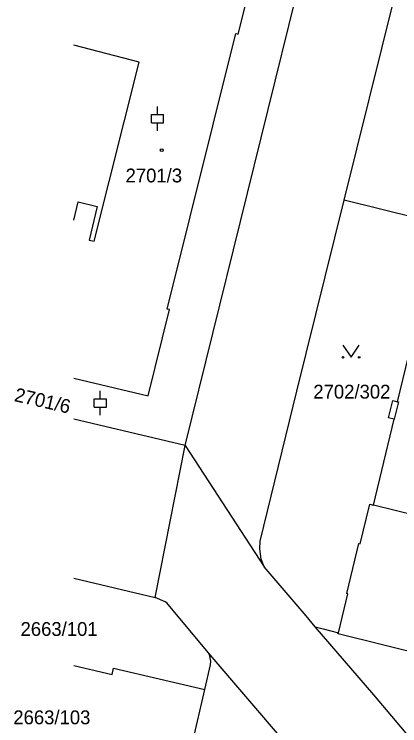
# Model space of a CAD drawing. Extents: x -496682 to -495907, y -1088575 to -1088018.
# Drawn here: x -496681.5 to -496634.1, y -1088524.5 to -1088436.9 of the extents above; entities that cross this region are included whole.
import ezdxf

# ---------------------------------------------------------------- set-up
doc = ezdxf.new("R2010")
doc.units = 0
for name, color, linetype in [('Hranice parcel', 7, 'Continuous'), ('Parcelní čísla', 7, 'Continuous'), ('Vnitřní kresba', 7, 'Continuous'), ('Značky budov', 7, 'Continuous'), ('Značky kultur', 7, 'Continuous')]:
    doc.layers.add(name, color=color, linetype=linetype)

msp = doc.modelspace()

# ---------------------------------------------------------------- linework, layer by layer
at = {"layer": 'Hranice parcel'}
for p, q in [((-496640.95, -1088459.81), (-496628.55, -1088409.94)), ((-496660.52, -1088489.98), (-496645.25, -1088428.29)), ((-496629.09, -1088462.74), (-496640.95, -1088459.81)), ((-496660.52, -1088489.98), (-496674.201, -1088486.739)), ((-496664.18, -1088508.68), (-496660.52, -1088489.98)), ((-496660.52, -1088489.98), (-496650.79, -1088504.94)), ((-496625.56, -1088500.2), (-496637.35, -1088497.34)), ((-496674.201, -1088506.316), (-496664.18, -1088508.68)), ((-496657.68, -1088515.47), (-496662.75, -1088509.37)), ((-496639.82, -1088536.3), (-496657.68, -1088515.47))]:
    msp.add_line(p, q, dxfattribs=at)
for points in [[(-496674.201, -1088481.706), (-496665.05, -1088483.89), (-496662.42, -1088473.27), (-496662.72, -1088473.21), (-496654.28, -1088439.31), (-496654, -1088439.38), (-496650.83, -1088426.78), (-496645.25, -1088428.29)], [(-496650.79, -1088504.94), (-496651.14, -1088503.97), (-496651.32, -1088502.72), (-496651.27, -1088501.75), (-496646.76, -1088483.31), (-496640.95, -1088459.81)], [(-496637.35, -1088497.34), (-496634.78, -1088486.77), (-496635.48, -1088486.6), (-496634.95, -1088484.46), (-496634.38, -1088484.6), (-496631.65, -1088473.31)], [(-496641.66, -1088513.05), (-496640.49, -1088508.23), (-496640.63, -1088508.19), (-496639.16, -1088502.05), (-496638.99, -1088502.09), (-496637.8, -1088497.21), (-496637.35, -1088497.34)], [(-496644.5, -1088512.3), (-496645.64, -1088510.97), (-496650.79, -1088504.94)], [(-496662.75, -1088509.37), (-496662.98, -1088509.24), (-496664.18, -1088508.68)], [(-496621.83, -1088538.93), (-496627.8, -1088531.94), (-496637.3, -1088520.68), (-496644.5, -1088512.3)], [(-496644.5, -1088512.3), (-496643.54, -1088512.55), (-496641.66, -1088513.05)], [(-496619.55, -1088518.48), (-496630.64, -1088516.04), (-496630.61, -1088515.92), (-496641.69, -1088513.15), (-496641.66, -1088513.05)], [(-496657.39, -1088516.99), (-496657.35, -1088516.539), (-496657.368, -1088516.313), (-496657.477, -1088515.874), (-496657.68, -1088515.47)], [(-496674.201, -1088517.051), (-496669.49, -1088518.17), (-496669.31, -1088517.4), (-496658.07, -1088520.03), (-496657.39, -1088516.99)]]:
    msp.add_lwpolyline(points, dxfattribs=at)
at = {"layer": 'Vnitřní kresba'}
for p, q in [((-496666.18, -1088442.82), (-496674.201, -1088440.723)), ((-496671.69, -1088464.87), (-496666.18, -1088442.82)), ((-496674.201, -1088462.263), (-496673.67, -1088460.03)), ((-496673.67, -1088460.03), (-496671.33, -1088460.58)), ((-496671.33, -1088460.58), (-496672.3, -1088464.73)), ((-496672.3, -1088464.73), (-496671.69, -1088464.87)), ((-496634.26, -1088484.62), (-496634.78, -1088486.77)), ((-496634.38, -1088484.6), (-496634.26, -1088484.62)), ((-496660.69, -1088531.17), (-496658.07, -1088520.03))]:
    msp.add_line(p, q, dxfattribs=at)
at = {"layer": 'Značky budov'}
msp.add_circle((-496663.387, -1088453.659), 0.175, dxfattribs=at)
at = {"layer": 'Značky kultur'}
for p, q in [((-496663.91, -1088449.271), (-496663.91, -1088448.27)), ((-496664.661, -1088449.271), (-496663.159, -1088449.271)), ((-496664.661, -1088450.272), (-496664.661, -1088449.271)), ((-496663.159, -1088450.272), (-496663.159, -1088449.271)), ((-496664.661, -1088450.272), (-496663.159, -1088450.272)), ((-496663.91, -1088451.27), (-496663.91, -1088450.272)), ((-496670.94, -1088484.261), (-496670.94, -1088483.26)), ((-496671.691, -1088484.261), (-496670.189, -1088484.261)), ((-496671.691, -1088485.262), (-496671.691, -1088484.261)), ((-496670.189, -1088485.262), (-496670.189, -1088484.261)), ((-496671.691, -1088485.262), (-496670.189, -1088485.262)), ((-496670.94, -1088486.26), (-496670.94, -1088485.262))]:
    msp.add_line(p, q, dxfattribs=at)
msp.add_lwpolyline([(-496641.1, -1088477.639), (-496640.1, -1088479.14), (-496639.1, -1088477.639)], dxfattribs=at)
for centre in [(-496641.1, -1088479.139), (-496639.1, -1088479.139)]:
    msp.add_circle(centre, 0.1, dxfattribs=at)

# ---------------------------------------------------------------- texts
at = {"layer": 'Parcelní čísla'}
for s, p in [('2701/3', (-496667.835, -1088457.62)), ('2702/302', (-496644.74, -1088484.22)), ('2663/101', (-496680.75, -1088513.42)), ('2663/103', (-496681.64, -1088524.29))]:
    msp.add_text(s, height=1.7, dxfattribs=at).set_placement(p)
msp.add_text('2701/6', height=1.7, rotation=347, dxfattribs=at).set_placement((-496681.612, -1088484.514))

doc.saveas('drawing.dxf')
